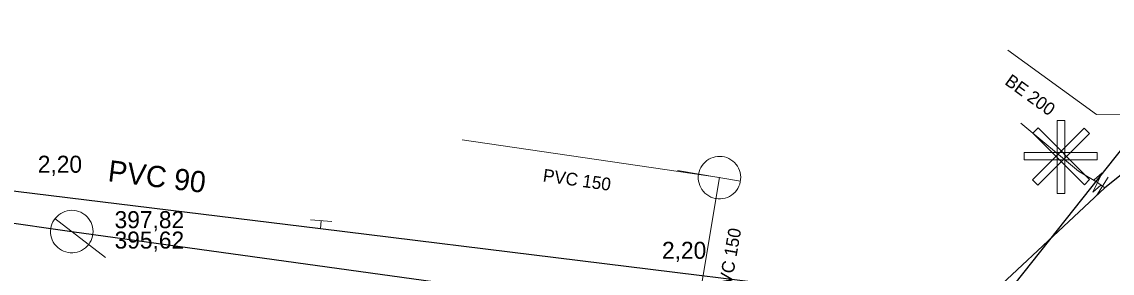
# Model space of a CAD drawing. Extents: x -809028 to -807737, y -990545 to -989489.
# Drawn here: x -808669.4 to -808618, y -990003.7 to -989991.8 of the extents above; entities that cross this region are included whole.
import ezdxf

# ---------------------------------------------------------------- set-up
doc = ezdxf.new("R2010")
doc.units = 0
doc.header["$LTSCALE"] = 0.32
for name, color, linetype, lineweight in [('1', 7, 'Continuous', 13), ('11', 7, 'Continuous', 13), ('12', 7, 'Continuous', 13), ('13', 7, 'Continuous', 13), ('14', 7, 'Continuous', 25), ('17', 7, 'Continuous', 25), ('22', 7, 'Continuous', 13), ('34', 7, 'Continuous', 13), ('47', 7, 'Continuous', 13)]:
    doc.layers.add(name, color=color, linetype=linetype, lineweight=lineweight)

msp = doc.modelspace()

# ---------------------------------------------------------------- linework, layer by layer
at = {"layer": '11'}
for p, q in [((-808648.636, -989997.388), (-808636.524, -989999.172)), ((-808636.524, -989999.172), (-808637.629, -990005.76))]:
    msp.add_line(p, q, dxfattribs=at)
msp.add_lwpolyline([(-808622.951, -989993.17), (-808618.788, -989996.198), (-808616.276, -989996.169)], dxfattribs=at)
at = {"layer": '12'}
for points in [[(-808619.365, -989996.844), (-808619.117, -989997.092), (-808621.546, -989999.521), (-808621.793, -989999.273)], [(-808621.784, -989997.083), (-808621.537, -989996.835), (-808619.108, -989999.264), (-808619.355, -989999.512)], [(-808620.631, -989996.48), (-808620.281, -989996.48), (-808620.281, -989999.915), (-808620.631, -989999.915)], [(-808618.747, -989997.989), (-808618.747, -989998.339), (-808622.182, -989998.339), (-808622.182, -989997.989)]]:
    msp.add_lwpolyline(points, close=True, dxfattribs=at)
at = {"layer": '13'}
msp.add_line((-808618.503, -989999.576), (-808618.737, -989999.398), dxfattribs=at)
msp.add_lwpolyline([(-808618.737, -989999.398), (-808619.631, -989998.868), (-808622.346, -989996.605)], dxfattribs=at)
at = {"layer": '14'}
for p, q in [((-808695.789, -989997.55), (-808666.999, -990001.71)), ((-808666.999, -990001.71), (-808639.396, -990005.515))]:
    msp.add_line(p, q, dxfattribs=at)
at = {"layer": '14', "lineweight": 13}
for p, q in [((-808618.388, -989999.647), (-808618.503, -989999.576)), ((-808655.3, -990001.572), (-808655.269, -990001.199))]:
    msp.add_line(p, q, dxfattribs=at)
at = {"layer": '14'}
msp.add_lwpolyline([(-808637.629, -990005.76), (-808625.384, -990007.653), (-808616.276, -989996.169), (-808606.504, -989991.842)], dxfattribs=at)
at = {"layer": '17'}
for points in [[(-808609.716, -989992.736), (-808618.388, -989999.647), (-808625.438, -990006.24)], [(-808694.1, -989996.799), (-808693.84, -989996.838), (-808693.67, -989996.855), (-808693.169, -989996.906), (-808674.318, -989999.243), (-808671.192, -989999.618), (-808655.3, -990001.572), (-808630.859, -990004.578), (-808627.827, -990005.523)]]:
    msp.add_lwpolyline(points, dxfattribs=at)
at = {"layer": '22'}
for p, q in [((-808638.496, -989998.84), (-808635.538, -989999.337)), ((-808665.41, -990002.925), (-808667.792, -990001.102))]:
    msp.add_line(p, q, dxfattribs=at)
for points in [[(-808636.689, -990000.158), (-808636.581, -990000.17), (-808636.472, -990000.17), (-808636.362, -990000.158), (-808636.256, -990000.135), (-808636.152, -990000.1), (-808636.052, -990000.054), (-808635.959, -989999.996), (-808635.873, -989999.93), (-808635.793, -989999.854), (-808635.723, -989999.77), (-808635.662, -989999.679), (-808635.612, -989999.581), (-808635.573, -989999.479), (-808635.545, -989999.373), (-808635.529, -989999.264), (-808635.525, -989999.156), (-808635.532, -989999.046), (-808635.551, -989998.938), (-808635.583, -989998.833), (-808635.625, -989998.733), (-808635.679, -989998.637), (-808635.742, -989998.548), (-808635.815, -989998.466), (-808635.896, -989998.393), (-808635.985, -989998.329), (-808636.081, -989998.275), (-808636.182, -989998.232), (-808636.286, -989998.2), (-808636.394, -989998.18), (-808636.503, -989998.172), (-808636.612, -989998.175), (-808636.721, -989998.191), (-808636.826, -989998.218), (-808636.929, -989998.257), (-808637.027, -989998.307), (-808637.118, -989998.367), (-808637.203, -989998.437), (-808637.279, -989998.515), (-808637.346, -989998.602), (-808637.403, -989998.695), (-808637.45, -989998.794), (-808637.486, -989998.897), (-808637.51, -989999.005), (-808637.522, -989999.113), (-808637.522, -989999.223), (-808637.511, -989999.331), (-808637.488, -989999.439), (-808637.452, -989999.543), (-808637.406, -989999.642), (-808637.35, -989999.736), (-808637.283, -989999.823), (-808637.207, -989999.901), (-808637.124, -989999.972), (-808637.032, -990000.032), (-808636.936, -990000.083), (-808636.833, -990000.122), (-808636.727, -990000.15)], [(-808666.39, -990000.916), (-808666.48, -990000.854), (-808666.577, -990000.803), (-808666.68, -990000.762), (-808666.784, -990000.733), (-808666.893, -990000.715), (-808667.002, -990000.71), (-808667.112, -990000.716), (-808667.219, -990000.735), (-808667.325, -990000.765), (-808667.426, -990000.806), (-808667.522, -990000.858), (-808667.612, -990000.921), (-808667.695, -990000.993), (-808667.769, -990001.073), (-808667.834, -990001.162), (-808667.889, -990001.256), (-808667.934, -990001.356), (-808667.967, -990001.461), (-808667.988, -990001.568), (-808667.998, -990001.676), (-808667.995, -990001.787), (-808667.981, -990001.895), (-808667.954, -990002.002), (-808667.917, -990002.104), (-808667.869, -990002.202), (-808667.809, -990002.294), (-808667.74, -990002.38), (-808667.663, -990002.457), (-808667.577, -990002.525), (-808667.484, -990002.583), (-808667.386, -990002.632), (-808667.283, -990002.668), (-808667.177, -990002.694), (-808667.068, -990002.708), (-808666.958, -990002.709), (-808666.85, -990002.699), (-808666.742, -990002.677), (-808666.638, -990002.643), (-808666.538, -990002.598), (-808666.444, -990002.542), (-808666.356, -990002.477), (-808666.276, -990002.402), (-808666.205, -990002.318), (-808666.143, -990002.228), (-808666.092, -990002.131), (-808666.051, -990002.03), (-808666.022, -990001.925), (-808666.004, -990001.816), (-808665.998, -990001.707), (-808666.004, -990001.598), (-808666.022, -990001.49), (-808666.053, -990001.384), (-808666.093, -990001.283), (-808666.146, -990001.187), (-808666.208, -990001.097), (-808666.28, -990001.014), (-808666.361, -990000.94)]]:
    msp.add_lwpolyline(points, close=True, dxfattribs=at)
at = {"layer": '34'}
for p, q in [((-808618.242, -989999.149), (-808618.764, -990000.002)), ((-808655.767, -990001.157), (-808654.77, -990001.241))]:
    msp.add_line(p, q, dxfattribs=at)
at = {"layer": '47'}
msp.add_line((-808618.512, -989998.94), (-808618.896, -989999.276), dxfattribs=at)
msp.add_lwpolyline([(-808618.512, -989998.94), (-808618.961, -989999.855), (-808618.577, -989999.519)], dxfattribs=at)

# ---------------------------------------------------------------- texts
at = {"layer": '1'}
for s, height, rotation, p in [('BE 200', 0.6, 324, (-808623.143, -989994.749)), ('PVC 90', 1, 353, (-808665.335, -989999.336)), ('PVC 150 ', 0.6, 352, (-808644.86, -989999.349)), ('PVC 150 ', 0.6, 80, (-808636.051, -990004.766))]:
    msp.add_text(s, height=height, rotation=rotation, dxfattribs=at).set_placement(p)
for p in [(-808668.599, -989998.941), (-808639.229, -990002.991)]:
    msp.add_text('2,20', height=0.8, dxfattribs=at).set_placement(p)
at = {"layer": '14'}
for s, p in [('397,82', (-808664.985, -990001.549)), ('395,62', (-808664.985, -990002.509))]:
    msp.add_text(s, height=0.8, dxfattribs=at).set_placement(p)

doc.saveas('drawing.dxf')
